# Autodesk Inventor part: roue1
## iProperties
Author: Administrateur
Shininess: 20.0
PropertySet Name: _Private Model Information
Length Units: 11269
Angle Units: 11283
Time Units: 11279
Mass Units: 11290
Length Display Precision: 3
Angle Display Precision: 2
Compacted: False
Created: 2001-04
Part Number: roue1
Material: Par défaut
Document SubType Name: Modélisation
Designer: Administrateur
Control State: 0
Master: False
Checked Out: False
PropertySet Name: Design Tracking Control
Density: 0.0
Volumn: 0.0
Area: 0.0
PropertySet Name: Model Information
